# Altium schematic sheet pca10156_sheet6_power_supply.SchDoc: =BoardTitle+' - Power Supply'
size A3; Organization: Nordic Semiconductor; DocumentNumber: 6; SheetNumber: 6; SheetTotal: 8; CompanyName: Nordic Semiconductor; DocumentSize: A4
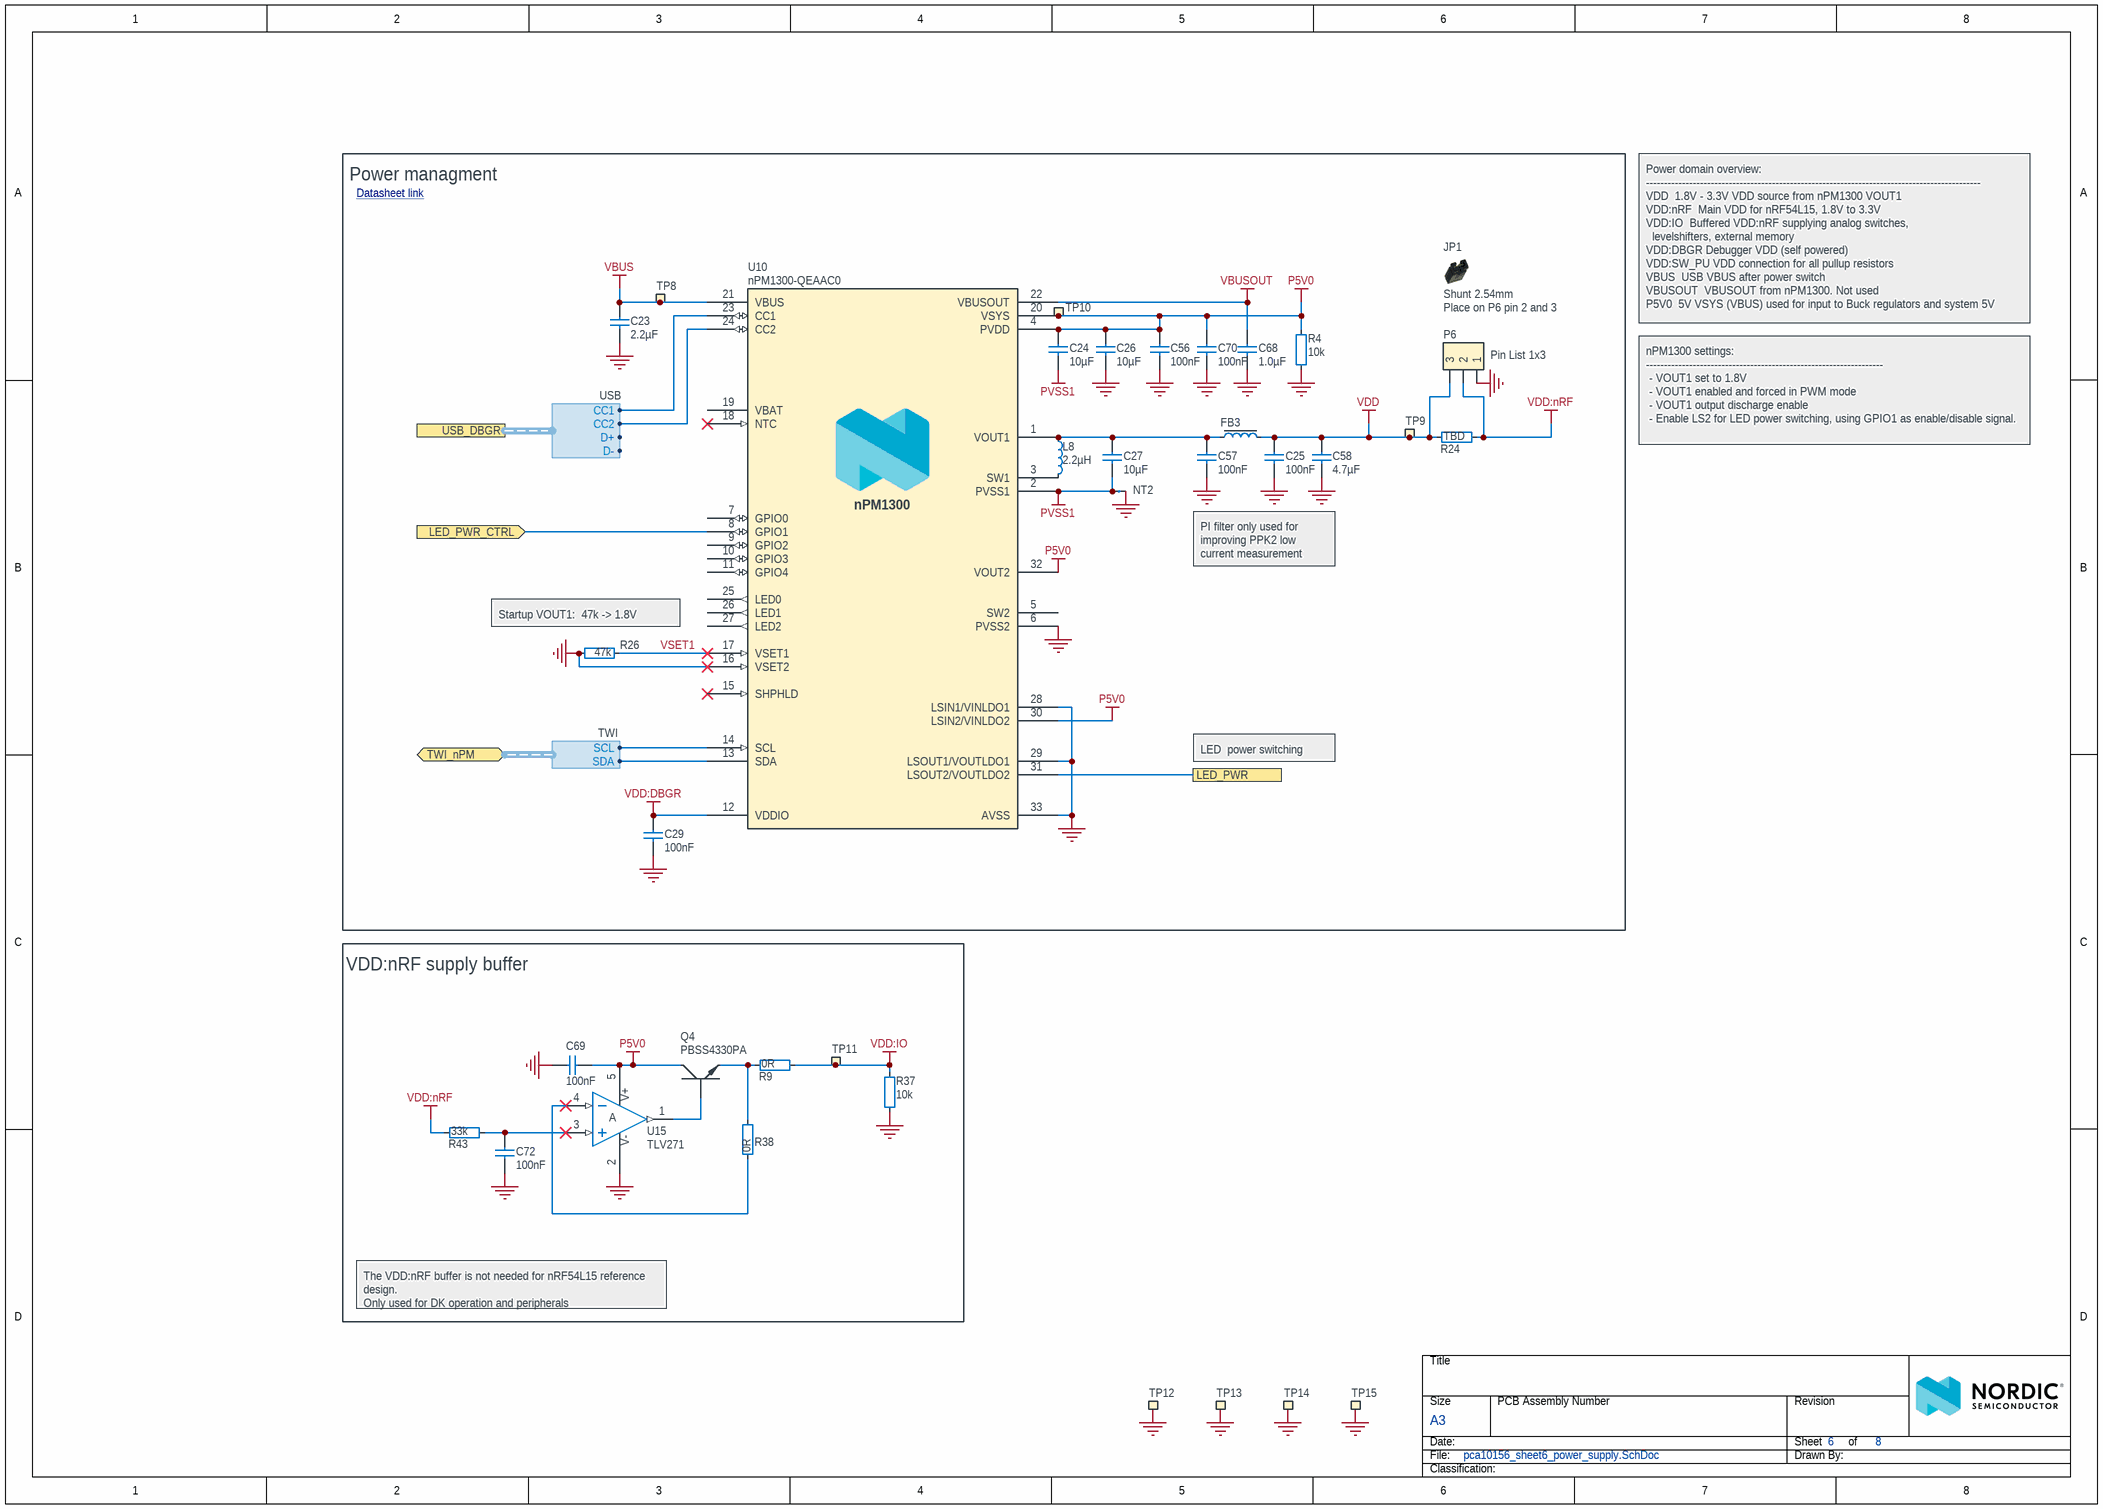
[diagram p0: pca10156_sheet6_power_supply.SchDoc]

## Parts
C23  2.2µF  [CAPC1005X04L]
C24  10µF  [CAPC1608X06L]
C25  100nF  [CAPC0603X03L_C]
C26  10µF  [CAPC1608X06L]
C27  10µF  [CAPC1608X06L]
C29  100nF  [CAPC0603X03L_C]
C56  100nF  [CAPC0603X03L_C]
C57  100nF  [CAPC0603X03L_C]
C58  4.7µF  [CAPC1608X06L]
C68  1.0µF  [CAPC1005X04L]
C69  100nF  [CAPC0603X03L_C]
C70  100nF  [CAPC0603X03L_C]
C72  100nF  [CAPC0603X03L_C]
FB3  120R/0.55A  [INDC1005X04L]  (value not drawn)
JP1  Shunt 2.54mm  Assembly: Place on P6 pin 2 and 3  [Shunt_2.54mm_Vertical]
L8  2.2µH  [INDC2016X10N]
NT2  Net tie  [2 PIN STARPOINT]  (value not drawn)  (net tie, no BOM)
P6  Pin List 1x3  [LIST_1x3_SMD]
Q4  PBSS4330PA  [DFN105P200X65-3N_v2]
R4  10k  [RESC0603X03L_C]
R9  0R  [RESC0603X03L_C]
R24  TBD  [RESC1005X04L]
R26  47k  [RESC0603X03L_C]
R37  10k  [RESC0603X03L_C]
R38  0R  [RESC0603X03L_C]
R43  33k  [RESC0603X03L_C]
TP8  Ø1.5mm,SMD  [TP_SMD_D1.5mm]  (value not drawn)  (no BOM)
TP9  Ø1.5mm,SMD  [TP_SMD_D1.5mm]  (value not drawn)  (no BOM)
TP10  Ø1.5mm,SMD  [TP_SMD_D1.5mm]  (value not drawn)  (no BOM)
TP11  Ø1.5mm,SMD  [TP_SMD_D1.5mm]  (value not drawn)  (no BOM)
TP12  Ø1.5mm,SMD  [TP_SMD_D1.5mm]  (value not drawn)  (no BOM)
TP13  Ø1.5mm,SMD  [TP_SMD_D1.5mm]  (value not drawn)  (no BOM)
TP14  Ø1.5mm,SMD  [TP_SMD_D1.5mm]  (value not drawn)  (no BOM)
TP15  Ø1.5mm,SMD  [TP_SMD_D1.5mm]  (value not drawn)  (no BOM)
U10  nPM1300-QEAAC0  [Nordic_QFN50P500X500X90-33N]
U15  TLV271  [SOT95P280X145-5N]

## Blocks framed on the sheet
Power managment: C23-C27 C29 C56-C58 C68 C70 FB3 JP1 L8 NT2 P6 R4 R24 R26 TP8-TP10 U10
VDD:nRF supply buffer: C69 C72 Q4 R9 R37 R38 R43 TP11 U15

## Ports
LED_PWR, LED_PWR_CTRL (in), TWI_nPM (bidir, harness TWI), USB_DBGR (harness USB)

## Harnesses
TWI: SDA, SCL
USB: D+, D-, CC1, CC2

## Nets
GND: C23.1 C25.1 C26.1 C29.2 C56.1 C57.1 C58.2 C68.1 C69.2 C70.1 C72.2 NT2.1 P6.1 R4.1 R26.2 R37.1 TP12.1 TP13.1 TP14.1 TP15.1 U10.6(PVSS2) U10.16(VSET2) U10.28(LSIN1/VINLDO1) U10.29(LSOUT1/VOUTLDO1) U10.33(AVSS) U15.2(VSS)
P5V0: C24.2 C26.2 C56.2 C69.1 C70.2 Q4.3(C) R4.2 TP10.1 U10.4(PVDD) U10.20(VSYS) U10.30(LSIN2/VINLDO2) U10.32(VOUT2) U15.5(VDD)
PVSS1: C24.1 C27.1 NT2.2 U10.2(PVSS1)
VBUS: C23.2 TP8.1 U10.21(VBUS)
VBUSOUT: C68.2 U10.22(VBUSOUT)
VDD: C25.2 C58.1 FB3.2 P6.3 R24.2 TP9.1
VDD:DBGR: C29.1 U10.12(VDDIO)
VDD:IO: R9.2 R37.2 TP11.1
VDD:nRF: P6.2 R24.1 R43.1
LED_PWR: U10.31(LSOUT2/VOUTLDO2) ; port LED_PWR
LED_PWR_CTRL: U10.8(GPIO1) ; port LED_PWR_CTRL
VSET1: R26.1 U10.17(VSET1)
NetC27_2: C27.2 C57.2 FB3.1 L8.1 U10.1(VOUT1)
NetC72_1: C72.1 R43.2 U15.3(IN+)
NetL8_2: L8.2 U10.3(SW1)
NetQ4_1: Q4.1(B) U15.1(OUT)
NetQ4_2: Q4.2(E) R9.1 R38.2
NetR38_1: R38.1 U15.4(IN-)
NetU10_13: U10.13(SDA) ; port TWI_nPM.SDA
NetU10_14: U10.14(SCL) ; port TWI_nPM.SCL
NetU10_23: U10.23(CC1) ; port USB_DBGR.CC1
NetU10_24: U10.24(CC2) ; port USB_DBGR.CC2

Not connected (* = marked no-connect by the designer): U10 5(SW2) 7(GPIO0) 9(GPIO2) 10(GPIO3) 11(GPIO4) 15(SHPHLD)* 18(NTC)* 19(VBAT) 25(LED0) 26(LED1) 27(LED2)

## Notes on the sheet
- Datasheet link <https://www.nordicsemi.com/Products/nPM1300>
- Power domain overview:
  ---------------------------------------------------------------------------------------------
  VDD		1.8V - 3.3V VDD source from nPM1300 VOUT1
  VDD:nRF		Main VDD for nRF54L15, 1.8V to 3.3V
  VDD:IO		Buffered VDD:nRF supplying analog switches,
  levelshifters, external memory
  VDD:DBGR	Debugger VDD (self powered)
  VDD:SW_PU	VDD connection for all pullup resistors
  VBUS		USB VBUS after power switch
  VBUSOUT		VBUSOUT from nPM1300. Not used
  P5V0		5V VSYS (VBUS) used for input to Buck regulators and system 5V
- nPM1300 settings:
  ------------------------------------------------------------------
  - VOUT1 set to 1.8V
  - VOUT1 enabled and forced in PWM mode
  - VOUT1 output discharge enable
  - Enable LS2 for LED power switching, using GPIO1 as enable/disable signal.
- PI filter only used for improving PPK2 low current measurement accuracy
- (near R26) Startup VOUT1:  47k -> 1.8V
- LED  power switching
- The VDD:nRF buffer is not needed for nRF54L15 reference design.
  Only used for DK operation and peripherals

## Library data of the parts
C23 = C0402-2µ2-10V: Capacitor, X5R, ±10%; Manufacturer: N.A.; Part number NEMS: 100200376; Component Status: Active; Pad Count: 2; Note: 10V
C24 C26 C27 = C0603-10µ-10V-X7T-GRM188D71A106MA73: Capacitor, X7T, ±20%, 10V; Manufacturer: Murata; Part number IPS: 00000004696; Part number NEMS: 100200414; Component Status: Active; Pad Count: 2; Note: 10VDC; Artikkelnr Noca: N.A.
C25 C56 C57 C70 = C0201-100n: Capacitor, X5R, ±10%; Manufacturer: N.A.; Part number IPS: 00000001248, 00000002505; Part number Norautron: 262071862; Part number NEMS: 100200078; Note: 16V; Pad Count: 2; Component Status: Active
C29 C69 C72 = C0201-100n: Capacitor, X5R, ±10%; Manufacturer: N.A.; Part number IPS: 00000001248, 00000002505; Part number Norautron: 262071862; Part number NEMS: 100200078; Pad Count: 2; Note: 16V; Component Status: Active
C58 = C0603-4µ7-10V-X7S: Capacitor, X7S, ±10%, 10V; Manufacturer: N.A.; Part number IPS: 00000001779; Part number NEMS: 100200351; Pad Count: 2; Artikkelnr Noca: 20030013; Component Status: Active
C68 = C0402-1µ0-6.3V-X5R-10%: Capacitor, X5R, ±10%, 6.3V; Manufacturer: N.A.; Part number Norautron: 26207137; Part number NEMS: 100200498; Pad Count: 2; Component Status: Active
FB3 = FB0402-120R@100M-500mA: Ferrite Bead, 120 Ohm @ 100MHz, 500mA, 250 mOhm Max; Manufacturer: Murata; Manufacturer Part Number: BLM15AG121SN1D; Part number IPS: 00000009954; Part number Norautron: 265230631; Part number NEMS: 100300099; Note: Chip EMIFIL Inductor Type Chip Ferrite Bead; Artikkelnr Noca: 33029317; Pad Count: 2; Component Status: Active
JP1 = SHUNT JUMPER 2.54mm Black Vertical: Shunt Jumper 2.54mm Black, open top; Manufacturer: WCON; Manufacturer Part Number: 3710-6001OS0B05; Part number NEMS: 100500728; Pad Count: 2; Note: N.A.; Component Status: Active; System: Connector
L8 = L0806-2µ2-2500mA-73mOhm-CIGT201610EH2R2MNE: Inductor, Irms=2.5A, Isat=2.9A, ±20%, DCR=73mΩ; Manufacturer: Samsung Electro-Mechanics America; Part number Norautron: 26521789; Part number NEMS: 100300400; Component Status: Active; Pad Count: 2; Note: Unshielded Thin Film Inductor; Artikkelnr Noca: N.A.
NT2 = 2 pin starpoint: Starpoint; Manufacturer: N.A.; Part number NEMS: 100500603; Pad Count: 2; Component Status: Active; System: Connector
P6 = Pin List 1x3 SMD: Pin List 1x3, 2.54mm (100mil), SMD; Manufacturer: WCON; Manufacturer Part Number: 1125-1103S0M116CR04; Part number Norautron: 26470016; Part number NEMS: 100500306; Note: N.A.; Pad Count: 3; Component Status: Active; System: Connector
Q4 = PBSS4330PA,115: 30V, 3A, 2.1W, G=270, NPN Transistor; Manufacturer: Nexperia; Part number NEMS: 101300184; Component Status: Active; Pad Count: 3; Note: N.A.
R4 R37 = R0201-10k: Resistor, ±1%, 0.05W; Manufacturer: N.A.; Part number IPS: 00000001255; Part number Norautron: 26107101; Part number NEMS: 100100065; Component Status: Active; Pad Count: 2; Note: Chip Res 1%
R9 R38 = R0201-0R: Resistor, ±5%, 0.05W; Manufacturer: N.A.; Part number IPS: 00000003245; Part number NEMS: 100100001; Component Status: Active; Pad Count: 2; Note: Chip Res 5%
R24 = R0402-TBD: Chip Res 0402; Manufacturer: N.A.; Part number NEMS: 100100282; Component Status: Active; Pad Count: 2
R26 = R0201-47k: Resistor, ±1%, 0.05W; Manufacturer: N.A.; Part number IPS: 00000001423; Part number NEMS: 100100076; Component Status: Active; Pad Count: 2; Note: Chip Res 1%
R43 = R0201-33k: Resistor, ±1%, 0.05W; Manufacturer: N.A.; Part number IPS: 00000001708; Part number NEMS: 100100073; Component Status: Active; Pad Count: 2; Note: Chip Res 1%
TP8-TP15 = TP_SMD_Ø1.5MM: 1.5mm circular SMD testpad; Manufacturer: Nordic Semiconductor; Manufacturer Part Number: N.A.; Part number NEMS: 100500477; Pad Count: 1; Component Status: Active
U10 = nPM1300-QEAAC0: Li-Ion/Li-Polymer USB-C battery charger with high efficiency buck regulators, LDOs or load switches, LED drivers, TWI and VBUSOUT; Manufacturer: Nordic Semiconductor; Part number NEMS: 102000306; Component Status: Active; Pad Count: 33; Note: Production version; Artikkelnr Noca: N.A.
U15 = TLV271CW5-7: Dual rail to rail CMOS Amplifier; Manufacturer: Diodes Incorporated; Part number NEMS: 101900398; Component Status: Active; Pad Count: 5; Note: N.A.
